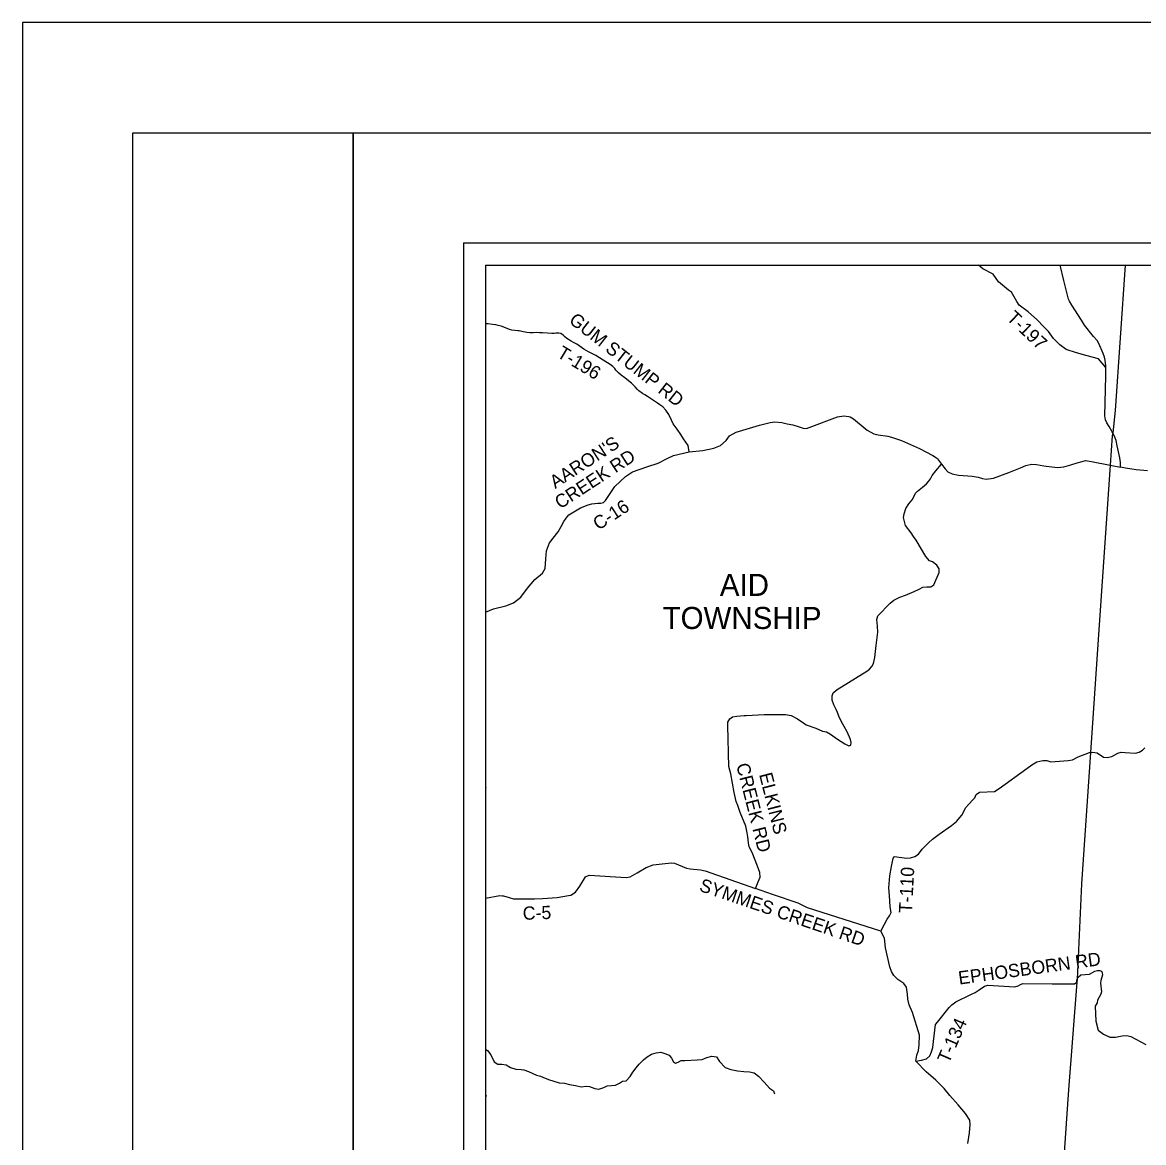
# Model space of a CAD drawing. Extents: x -6.4 to 34, y -1.2 to 22.
# Drawn here: x 0 to 5.08, y 16.92 to 22 of the extents above; entities that cross this region are included whole.
import ezdxf

# ---------------------------------------------------------------- set-up
doc = ezdxf.new("R2010")
doc.units = 0
for name, color, linetype in [('GM_X_County', 7, 'Continuous'), ('GM_X_Minor_Lake', 7, 'Continuous'), ('GM_X_Minor_River', 7, 'Continuous'), ('GM_X_Minor_River_Text', 7, 'Continuous'), ('GM_X_Section', 7, 'Continuous'), ('GM_X_Township', 7, 'Continuous'), ('GM_X_Township_ROW', 7, 'Continuous'), ('GM_X_Township_Subdivision', 7, 'Continuous'), ('GM_X_Township_Subdivision_Text', 7, 'Continuous'), ('GM_X_Township_Text', 7, 'Continuous')]:
    doc.layers.add(name, color=color, linetype=linetype)

msp = doc.modelspace()

# ---------------------------------------------------------------- linework, layer by layer
at = {"layer": 'GM_X_County'}
for points in [[(0.5, 21.5), (1.5, 21.5), (1.5, 0.5), (0.5, 0.5)], [(1.5, 21.5), (33.5, 21.5), (33.5, 0.5), (1.5, 0.5)]]:
    msp.add_lwpolyline(points, close=True, dxfattribs=at)
at = {"layer": 'GM_X_Minor_Lake'}
msp.add_lwpolyline([(5.101, 19.9666), (5.0495, 19.9712), (5.0018, 19.9787), (4.9787, 19.9832), (4.9791, 20.0049), (4.976, 20.0266), (4.9646, 20.081), (4.9597, 20.1046), (4.9538, 20.1203), (4.9437, 20.1395), (4.9413, 20.144), (4.9284, 20.1674), (4.9169, 20.1842), (4.9117, 20.1976), (4.9082, 20.217), (4.9131, 20.3965), (4.9131, 20.4362), (4.913, 20.4436), (4.9092, 20.4691), (4.9064, 20.4828), (4.9006, 20.4996), (4.8815, 20.5443), (4.8734, 20.5577), (4.8574, 20.5758), (4.8164, 20.6276), (4.8016, 20.6503), (4.759, 20.7188), (4.7482, 20.7357), (4.7434, 20.7453), (4.7215, 20.8295), (4.7055, 20.9)], dxfattribs=at)
at = {"layer": 'GM_X_Minor_River'}
for points in [[(2.1, 19.3265), (2.1363, 19.3419), (2.1918, 19.3549), (2.2271, 19.3693), (2.2593, 19.3943), (2.2904, 19.4346), (2.3235, 19.4748), (2.3576, 19.5029), (2.3701, 19.5245), (2.3739, 19.5682), (2.3762, 19.605), (2.3907, 19.6407), (2.4293, 19.6901), (2.4428, 19.7148), (2.455, 19.737), (2.4651, 19.753), (2.4776, 19.7672), (2.5299, 19.799), (2.5656, 19.8123), (2.5826, 19.8176), (2.6097, 19.8201), (2.6229, 19.8204), (2.6346, 19.8237), (2.6441, 19.8319), (2.6869, 19.8962), (2.7351, 19.9417), (2.7659, 19.963), (2.8318, 19.9857), (2.8823, 20.0017), (2.9233, 20.0225), (2.9528, 20.0362), (3.023, 20.053), (3.0859, 20.0589), (3.1352, 20.0699), (3.166, 20.0817), (3.191, 20.1041), (3.2069, 20.1257), (3.2358, 20.1417), (3.3423, 20.1747), (3.3901, 20.1857), (3.4121, 20.1891), (3.4436, 20.186), (3.4675, 20.1807), (3.4929, 20.175), (3.5175, 20.1678), (3.5403, 20.1609), (3.5547, 20.1594), (3.6957, 20.2111), (3.7241, 20.2157), (3.7471, 20.2138), (3.7527, 20.2118), (3.769, 20.2024), (3.8304, 20.1511), (3.8613, 20.1351), (3.8732, 20.1318), (3.875, 20.1313)], [(3.875, 20.1313), (3.8801, 20.1299), (3.9242, 20.124), (3.9405, 20.12), (3.9855, 20.1041), (4.0673, 20.0681), (4.128, 20.0366), (4.1454, 20.0261), (4.1496, 20.0211), (4.1672, 19.9978), (4.184, 19.9763), (4.1966, 19.963), (4.2164, 19.9533), (4.2452, 19.9481), (4.2873, 19.9441), (4.3066, 19.9423), (4.3343, 19.9382), (4.3537, 19.9319), (4.37, 19.9289), (4.4037, 19.9344), (4.4733, 19.9598), (4.5262, 19.9805), (4.55, 19.9905), (4.5762, 19.9967), (4.5981, 19.9957), (4.6315, 19.9902), (4.6672, 19.985), (4.6945, 19.9817), (4.7229, 19.9853), (4.7539, 19.9941), (4.7834, 20.0034), (4.8057, 20.01), (4.8197, 20.0142), (4.8478, 20.0098), (4.9329, 19.9925), (4.9787, 19.9832)], [(3.2812, 18.8577), (3.3639, 18.8622), (3.4595, 18.8624), (3.4853, 18.8572), (3.515, 18.8422), (3.5477, 18.8193), (3.5534, 18.8155), (3.5984, 18.8), (3.6277, 18.7872), (3.6467, 18.7831), (3.6641, 18.7726), (3.6961, 18.7507), (3.7284, 18.7292), (3.7478, 18.7209), (3.7565, 18.7229), (3.7583, 18.7358), (3.7556, 18.7487), (3.7391, 18.7843), (3.7257, 18.8078), (3.7135, 18.8298), (3.702, 18.854), (3.6954, 18.8714), (3.6904, 18.8851), (3.6793, 18.9063), (3.6716, 18.9272), (3.6722, 18.9469), (3.6767, 18.9602), (3.6937, 18.9751), (3.8285, 19.0582), (3.8417, 19.0673), (3.8523, 19.0795), (3.859, 19.094), (3.8645, 19.1202), (3.8715, 19.1754), (3.879, 19.2354), (3.8777, 19.2635), (3.8749, 19.2931), (3.8786, 19.3094), (3.9347, 19.3678), (3.9513, 19.3812), (3.9778, 19.3938), (4.0043, 19.4031), (4.0432, 19.42), (4.0659, 19.4307), (4.0821, 19.4395), (4.1014, 19.4415), (4.1185, 19.4404), (4.1321, 19.4504), (4.1575, 19.5067), (4.1567, 19.5223), (4.1456, 19.5401), (4.127, 19.554), (4.1133, 19.5589), (4.0961, 19.579), (4.0532, 19.6521), (4.0403, 19.6699), (4.0296, 19.6861), (4.0044, 19.7191), (3.9958, 19.7551), (3.9976, 19.7718), (4.005, 19.7969), (4.0201, 19.8179), (4.034, 19.835), (4.043, 19.8529), (4.0501, 19.8651), (4.0588, 19.8754), (4.0807, 19.8937), (4.0992, 19.9079), (4.109, 19.9182), (4.1176, 19.9311), (4.1255, 19.946), (4.1424, 19.9677), (4.1672, 19.9978)], [(2.476, 18.0418), (2.4862, 18.0436), (2.5073, 18.0574), (2.5276, 18.0844), (2.5536, 18.1256), (2.5691, 18.134), (2.7375, 18.1239), (2.7553, 18.1267), (2.7878, 18.144), (2.829, 18.1689), (2.8596, 18.1804), (2.9422, 18.1904), (2.957, 18.1889), (3.0117, 18.1657), (3.0281, 18.1624), (3.0743, 18.1577), (3.0956, 18.1537), (3.3235, 18.0741), (3.3358, 18.103), (3.3448, 18.1251), (3.3439, 18.1467), (3.3336, 18.174), (3.309, 18.2361), (3.2948, 18.2618), (3.2917, 18.2804), (3.29, 18.3077), (3.2865, 18.3259), (3.2795, 18.3559), (3.2549, 18.4176), (3.2434, 18.449), (3.2357, 18.4672), (3.2275, 18.5089), (3.2115, 18.5927), (3.2037, 18.6268), (3.2015, 18.6852), (3.1996, 18.755), (3.1982, 18.8086), (3.1981, 18.8275), (3.2071, 18.842), (3.2192, 18.8523), (3.2392, 18.8555), (3.2733, 18.8573), (3.2812, 18.8577)], [(4.2862, 16.9173), (4.2952, 16.9655), (4.298, 17.0038), (4.2955, 17.0236), (4.2767, 17.0537), (4.2436, 17.093), (4.2059, 17.1353), (4.1795, 17.1666), (4.1418, 17.204), (4.0976, 17.2418), (4.0509, 17.2907), (4.0552, 17.3172), (4.0638, 17.3397), (4.0663, 17.3647), (4.0672, 17.408), (4.0363, 17.5108), (4.0213, 17.5457), (4.0155, 17.5715), (4.0139, 17.595), (4.0091, 17.6261), (3.9973, 17.6428), (3.9695, 17.6613), (3.9512, 17.6783), (3.9401, 17.6976), (3.9336, 17.7181), (3.9141, 17.8049), (3.9086, 17.8482), (3.8925, 17.88), (3.5603, 17.9852), (3.5168, 18.0065), (3.4017, 18.0457), (3.3235, 18.0741)], [(2.1, 18.0303), (2.1654, 18.041), (2.1768, 18.0408), (2.1817, 18.0407), (2.2068, 18.0333), (2.2273, 18.0262), (2.2664, 18.026), (2.3221, 18.0259), (2.359, 18.0285)], [(2.359, 18.0285), (2.359, 18.0285), (2.4252, 18.033), (2.4755, 18.0417), (2.476, 18.0418)]]:
    msp.add_lwpolyline(points, dxfattribs=at)
at = {"layer": 'GM_X_Minor_River_Text'}
for p, q in [((2.1, 18.5349), (2.1014, 18.5298)), ((2.1063, 17.1312), (2.1, 17.1327))]:
    msp.add_line(p, q, dxfattribs=at)
for points in [[(4.9131, 20.4362), (4.8792, 20.4751), (4.828, 20.4885), (4.7798, 20.5027), (4.7324, 20.5165), (4.704, 20.5378), (4.6748, 20.5675), (4.6529, 20.598), (4.6294, 20.622), (4.6025, 20.6502), (4.5609, 20.6883), (4.5196, 20.7188), (4.5098, 20.734), (4.4856, 20.777), (4.4708, 20.7854), (4.4253, 20.8239), (4.4019, 20.8589), (4.3545, 20.8826), (4.3348, 20.8998), (4.3347, 20.9)], [(3.023, 20.053), (3.0192, 20.0826), (2.9981, 20.1121), (2.9857, 20.1324), (2.9686, 20.1557), (2.9514, 20.1799), (2.9436, 20.1962), (2.9304, 20.2219), (2.9172, 20.2421), (2.9039, 20.2577), (2.8907, 20.2663), (2.879, 20.2744), (2.8479, 20.2951), (2.8343, 20.3036), (2.8226, 20.311), (2.8121, 20.3173), (2.7957, 20.3293), (2.7887, 20.3363), (2.7786, 20.348), (2.7681, 20.3585), (2.7619, 20.3644), (2.7486, 20.3749), (2.7315, 20.3893), (2.7144, 20.4013), (2.7023, 20.4119), (2.6906, 20.4231), (2.6856, 20.4317), (2.6774, 20.4407), (2.6653, 20.4484), (2.6334, 20.4691), (2.6003, 20.4901), (2.5817, 20.4983), (2.5665, 20.5064), (2.5451, 20.5181), (2.524, 20.5337), (2.5139, 20.5419), (2.4995, 20.5493), (2.4878, 20.5551), (2.4684, 20.5672), (2.4579, 20.5761), (2.452, 20.5823), (2.4415, 20.5901), (2.4326, 20.5913), (2.4189, 20.5913), (2.4108, 20.5901), (2.401, 20.5893), (2.3808, 20.5909), (2.3582, 20.5925), (2.3446, 20.5932), (2.3302, 20.594), (2.3162, 20.5932), (2.3002, 20.5928), (2.287, 20.5948), (2.2644, 20.5991), (2.2531, 20.6018), (2.2469, 20.6022), (2.2333, 20.6026), (2.2197, 20.6041), (2.2091, 20.608), (2.1912, 20.615), (2.1702, 20.6224), (2.157, 20.6259), (2.1473, 20.6283), (2.1309, 20.6302), (2.1118, 20.6333), (2.1041, 20.6337), (2.1, 20.6348)], [(4.8629, 18.6906), (4.8734, 18.6887), (4.9018, 18.6689), (4.9185, 18.6666), (4.9394, 18.6726), (4.9675, 18.6874), (4.982, 18.6915), (4.9998, 18.6907), (5.0465, 18.6872), (5.064, 18.6917), (5.0795, 18.7), (5.089, 18.7114)], [(3.9516, 18.2164), (3.9516, 18.2165), (3.9524, 18.2184), (4.0104, 18.2114), (4.0271, 18.2121), (4.0461, 18.2181), (4.0632, 18.2295), (4.08, 18.2511), (4.1085, 18.2807), (4.126, 18.2977), (4.1576, 18.3197), (4.2134, 18.3595), (4.2351, 18.3765), (4.2595, 18.4065), (4.2774, 18.4406), (4.2915, 18.4565), (4.3101, 18.4747), (4.3189, 18.4842), (4.3246, 18.5001), (4.3398, 18.5104), (4.4085, 18.5136), (4.4294, 18.5269), (4.5537, 18.6174), (4.5773, 18.634), (4.6001, 18.6476), (4.6274, 18.654), (4.6453, 18.654), (4.6638, 18.6475), (4.7417, 18.653), (4.7622, 18.6575), (4.7876, 18.6703), (4.8389, 18.6896), (4.8429, 18.6903), (4.8541, 18.6922), (4.8628, 18.6907), (4.8629, 18.6906)], [(3.8925, 17.88), (3.9072, 17.9088), (3.921, 17.935), (3.9312, 17.949), (3.9389, 17.965), (3.9351, 17.9905), (3.9311, 18.041), (3.9285, 18.0767), (3.9336, 18.1314), (3.9409, 18.1732), (3.9459, 18.1964), (3.9486, 18.2089), (3.9516, 18.2164)], [(4.7815, 17.6551), (4.7822, 17.662), (4.7871, 17.671), (4.7994, 17.6818), (4.8182, 17.6829), (4.839, 17.6852), (4.8629, 17.6979), (4.8743, 17.7023), (4.8847, 17.7014), (4.8937, 17.6984), (4.8967, 17.6916), (4.897, 17.6818), (4.8904, 17.6565), (4.8888, 17.6448), (4.8923, 17.605), (4.8904, 17.5949), (4.8754, 17.5666), (4.8733, 17.5554), (4.8646, 17.5398), (4.8679, 17.4717), (4.8784, 17.4318), (4.9027, 17.4131), (4.9303, 17.4001), (4.9569, 17.3989), (4.9869, 17.4049), (5.0078, 17.4068), (5.026, 17.4018), (5.0934, 17.3655)], [(4.0509, 17.2907), (4.0775, 17.2951), (4.0995, 17.3018), (4.114, 17.3147), (4.1214, 17.3334), (4.1279, 17.3528), (4.1309, 17.3802), (4.1403, 17.4561), (4.1498, 17.4675), (4.2024, 17.5334), (4.2142, 17.546), (4.2328, 17.5596), (4.3, 17.5932), (4.3198, 17.6012), (4.3384, 17.614), (4.3631, 17.6303), (4.3776, 17.6352), (4.5001, 17.6281), (4.5157, 17.6322), (4.5252, 17.6375), (4.5362, 17.6424), (4.6697, 17.641), (4.7708, 17.641), (4.7809, 17.6483), (4.7815, 17.6551)], [(2.1, 17.3448), (2.1095, 17.3387), (2.1235, 17.3189), (2.139, 17.2874), (2.1553, 17.2775), (2.1743, 17.2764), (2.1937, 17.2734), (2.2134, 17.2623), (2.2374, 17.2543), (2.2613, 17.2532), (2.2738, 17.2513), (2.2943, 17.2437), (2.3304, 17.2266), (2.349, 17.2232), (2.3596, 17.2186), (2.3858, 17.2068), (2.4097, 17.1992), (2.4337, 17.1927), (2.4587, 17.1908), (2.4811, 17.1855), (2.5085, 17.1805), (2.5335, 17.1748), (2.5567, 17.1771), (2.5719, 17.1756), (2.5954, 17.1672), (2.6133, 17.1634), (2.6361, 17.1714), (2.652, 17.1786), (2.671, 17.1797), (2.6893, 17.182), (2.7075, 17.1903), (2.7216, 17.1998), (2.7379, 17.2013), (2.7554, 17.2207), (2.7679, 17.2412), (2.7832, 17.2606), (2.7972, 17.2776), (2.8155, 17.2966), (2.8333, 17.311), (2.8519, 17.322), (2.8732, 17.3281), (2.8949, 17.3315), (2.9135, 17.3254), (2.9332, 17.3178), (2.9431, 17.3049), (2.9522, 17.2874), (2.9609, 17.2821), (2.9731, 17.2855), (2.9875, 17.2943), (3.0038, 17.2939), (3.0601, 17.2973), (3.0829, 17.298), (3.1038, 17.3075), (3.1265, 17.3128), (3.1478, 17.3101), (3.1607, 17.2885), (3.1861, 17.2623), (3.2127, 17.2528), (3.2351, 17.2478)], [(3.2351, 17.2478), (3.2358, 17.2477), (3.242, 17.2463), (3.2708, 17.244), (3.2966, 17.2425), (3.3179, 17.2379), (3.3373, 17.2227), (3.3627, 17.1957), (3.3874, 17.1688), (3.4052, 17.1562), (3.4108, 17.1424)]]:
    msp.add_lwpolyline(points, dxfattribs=at)
at = {"layer": 'GM_X_Section'}
msp.add_lwpolyline([(0, 0), (34, 0), (34, 22), (0, 22)], close=True, dxfattribs=at)
at = {"layer": 'GM_X_Township'}
for p, q in [((2, 21), (9, 21)), ((2, 21), (2, 14)), ((2.1, 20.9), (2.1, 14.1)), ((2.1, 20.9), (8.9, 20.9))]:
    msp.add_line(p, q, dxfattribs=at)
at = {"layer": 'GM_X_Township_ROW'}
msp.add_lwpolyline([(5.0001, 20.9), (4.9545, 20.2404), (4.9437, 20.1395), (4.9421, 20.1251), (4.9329, 19.9925), (4.8778, 19.2029), (4.8429, 18.6903), (4.8024, 18.0941), (4.7822, 17.662), (4.7809, 17.6483), (4.7438, 17.1604), (4.7383, 17.0951), (4.704, 16.5887)], dxfattribs=at)

# ---------------------------------------------------------------- texts
at = {"layer": 'GM_X_Township_Subdivision'}
for s, rotation, p in [('T-197', 316.4464, (4.4591, 20.6554)), ('GUM STUMP RD', 321.8858, (2.4742, 20.6416)), ('T-196', 328.9197, (2.4193, 20.4858)), ('T-110', 87.104, (4.0336, 17.9605)), ('EPHOSBORN RD', 7.807, (4.2479, 17.6376)), ('T-134', 66.4299, (4.2011, 17.2767))]:
    msp.add_text(s, height=0.06, rotation=rotation, dxfattribs=at).set_placement(p)
at = {"layer": 'GM_X_Township_Subdivision_Text'}
for s, p in [('AID', (3.1623, 19.4)), ('TOWNSHIP', (2.9028, 19.25))]:
    msp.add_text(s, height=0.1, dxfattribs=at).set_placement(p)
at = {"layer": 'GM_X_Township_Text'}
for s, rotation, p in [("AARON'S", 33.1008, (2.4159, 19.8845)), ('CREEK RD', 33.1008, (2.4386, 19.7919)), ('C-16', 33.1008, (2.612, 19.6955)), ('CREEK RD', 284.2467, (3.2361, 18.634)), ('ELKINS', 284.2467, (3.3399, 18.5907)), ('SYMMES CREEK RD', 341.1639, (3.0649, 18.0638)), ('C-5', 1.973, (2.2696, 17.9311))]:
    msp.add_text(s, height=0.06, rotation=rotation, dxfattribs=at).set_placement(p)

doc.saveas('drawing.dxf')
